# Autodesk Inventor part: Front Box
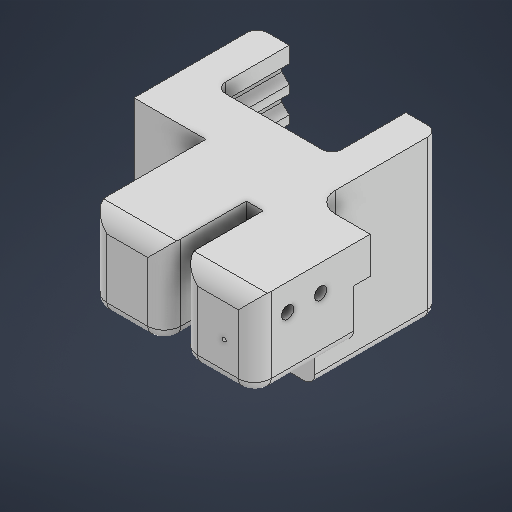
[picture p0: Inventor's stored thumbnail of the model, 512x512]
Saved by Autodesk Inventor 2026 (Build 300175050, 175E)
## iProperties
Created: 2023-12
Part Number: Front Box
Material: Generic
Document SubType Name: Modeling
Designer: Andrew
Density: 1 g/cm^3
Appearance: Default
Author: Andrew
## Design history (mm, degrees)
sketch "Sketch1"
  geometry: L1 (76.2, -76.2)-(-76.2, -76.2); L2 (-76.2, -76.2)-(-76.2, 76.2); L3 (-76.2, 76.2)-(76.2, 76.2); L4 (76.2, 76.2)-(76.2, -76.2); 1 further point
  constraints: 8 end point, 2 parallel, 1 horizontal, 1 perpendicular
  dimensions: "d0" = 152.4 distance between parallel lines of L3 L1 (derived); "d1" = 152.4 distance between parallel lines of L4 L2; "d2" = 76.2 distance from line of point (0, 0) L1 (= 0.5 x d0); "d3" = 76.2 distance from line of L2 point (0, 0) (= 0.5 x d1)
extrude "Extrusion1" new body sketch "Sketch1" distance "d4" = 5.08; taper "d5" = 0 deg
sketch "Sketch2"
  geometry: L1 (-76.2, -76.2)-(76.2, -76.2) reference; L2 (76.2, -76.2)-(76.2, 76.2) reference; L3 (76.2, 76.2)-(-76.2, 76.2) reference; L4 (-76.2, 76.2)-(-76.2, -76.2) reference; L5 (-71.12, 71.12)-(71.12, 71.12); L6 (71.12, 71.12)-(71.12, -71.12); L7 (71.12, -71.12)-(-71.12, -71.12); L8 (-71.12, -71.12)-(-71.12, 71.12); L9 (-71.12, 2.54)-(71.12, 2.54); L10 (71.12, 2.54)-(71.12, -2.54); L11 (71.12, -2.54)-(-71.12, -2.54); L12 (-71.12, -2.54)-(-71.12, 2.54); L13 (-2.54, 71.12)-(2.54, 71.12); L14 (2.54, 71.12)-(2.54, -71.12); L15 (2.54, -71.12)-(-2.54, -71.12); L16 (-2.54, -71.12)-(-2.54, 71.12); 11 further points
  constraints: 24 end point, 6 parallel, 4 point on line, 3 horizontal, 3 perpendicular, 2 midpoint
  dimensions: "d6" = 5.08 distance between parallel lines of L5 L3; "d7" = 5.08 distance between parallel lines of L4 L8; "d8" = 5.08 distance between parallel lines of L2 L6; "d9" = 5.08 distance between parallel lines of L1 L7; "d10" = 5.08 distance between parallel lines of L11 L9; "d11" = 5.08 distance between parallel lines of L16 L14; "d207" = 152.4 distance between parallel lines of L1 L3 (derived); "d208" = 76.2 distance from line of L1 point (-71.12, 0) (derived); "d209" = 76.2 distance from line of point (0, -71.12) L4 (derived)
extrude "Extrusion2" join sketch "Sketch2" distance "d14" = 25.4; taper "d15" = 0 deg
sketch "Sketch3"
  geometry: L1 (0, 30.48)-(152.4, 30.48) reference; L2 (104.14, 30.48)-(93.98, 30.48); L3 (93.98, 30.48)-(93.98, -19.05); L4 (93.98, -19.05)-(104.14, -19.05); L5 (104.14, -19.05)-(104.14, 30.48); L6 (58.42, 30.48)-(48.26, 30.48); L7 (48.26, 30.48)-(48.26, -19.05); L8 (48.26, -19.05)-(58.42, -19.05); L9 (58.42, -19.05)-(58.42, 30.48); L10 (152.4, 0)-(152.4, 30.48) reference; L11 (0, 0)-(152.4, 0) reference; 7 further points
  constraints: 16 end point, 5 midpoint, 4 parallel, 3 point on line, 2 horizontal, 2 perpendicular
  dimensions: "d18" = 10.16 distance from line of L3 point (104.14, 5.715); "d19" = 10.16 distance from line of L7 point (58.42, 5.715); "d20" = 35.56 distance between parallel lines of L9 L3; "d173" = 19.05 distance between parallel lines of L11 L4; "d198" = 17.78 distance from line of point (76.2, 30.48) L3 (derived)
extrude "Extrusion3" join sketch "Sketch3" distance "d23" = 38.1; taper "d24" = 0 deg
sketch "Sketch4"
  geometry: L1 (93.98, 30.48)-(93.98, -19.05) reference; L2 (93.98, 25.4)-(58.42, 25.4); L3 (58.42, 25.4)-(58.42, 30.48); L4 (58.42, 30.48)-(93.98, 30.48); L5 (93.98, 30.48)-(93.98, 25.4); L6 (58.42, -19.05)-(58.42, 30.48) reference; L7 (58.42, 30.48)-(93.98, 30.48) reference; 2 further points
  constraints: 8 end point, 2 parallel, 1 horizontal, 1 perpendicular, 1 point on line
  dimensions: "d25" = 0 distance between parallel lines of L6 L3; "d26" = 0 distance between parallel lines of L7 L4; "d27" = 5.08 distance between parallel lines of L4 L2
extrude "Extrusion4" join sketch "Sketch4" stored distance "d28" = 25.4; taper "d29" = 0 deg
sketch "Sketch5"
  geometry: L1 (7.62, -33.02)-(48.26, -33.02); L2 (48.26, -33.02)-(48.26, 0); L3 (48.26, 0)-(7.62, 0); L4 (7.62, 0)-(7.62, -33.02); L5 (104.14, 0)-(-48.26, 0) reference; L6 (10.16, -38.1)-(0, -38.1) reference; L7 (45.72, -38.1)-(10.16, -38.1) reference; 6 further points; 2 other entities
  constraints: 8 end point, 2 parallel, 1 horizontal, 1 midpoint, 1 perpendicular, 2 other
  dimensions: "d32" = 33.02 distance between parallel lines of L1 L3; "d174" = 2.54 dimension on L4; "d175" = 2.54 dimension on L2; "d177" = 38.1 distance between parallel lines of L6 L3
extrude "Extrusion5" cut sketch "Sketch5" distance "d34" = 2.54; taper "d35" = 0 deg
sketch "Sketch8"
  geometry: L1 (55.88, 25.4)-(96.52, 25.4); L2 (96.52, 25.4)-(96.52, 19.812); L3 (96.52, 19.812)-(55.88, 19.812); L4 (55.88, 19.812)-(55.88, 25.4); L5 (58.42, -19.05)-(58.42, 25.4) reference; L6 (93.98, 25.4)-(93.98, -19.05) reference; L7 (96.52, 11.684)-(55.88, 11.684); L8 (55.88, 11.684)-(55.88, 17.272); L9 (55.88, 17.272)-(96.52, 17.272); L10 (96.52, 17.272)-(96.52, 11.684); L11 (96.52, 3.556)-(55.88, 3.556); L12 (55.88, 3.556)-(55.88, 9.144); L13 (55.88, 9.144)-(96.52, 9.144); L14 (96.52, 9.144)-(96.52, 3.556); L15 (96.52, -4.572)-(55.88, -4.572); L16 (55.88, -4.572)-(55.88, 1.016); L17 (55.88, 1.016)-(96.52, 1.016); L18 (96.52, 1.016)-(96.52, -4.572); L19 (96.52, -12.7)-(55.88, -12.7); L20 (55.88, -12.7)-(55.88, -7.112); L21 (55.88, -7.112)-(96.52, -7.112); L22 (96.52, -7.112)-(96.52, -12.7); L23 (96.52, -15.24)-(55.88, -15.24); L24 (55.88, -15.24)-(55.88, -20.828); L25 (55.88, -20.828)-(96.52, -20.828); L26 (96.52, -20.828)-(96.52, -15.24); L27 (96.52, -28.956)-(55.88, -28.956); L28 (55.88, -28.956)-(55.88, -23.368); L29 (55.88, -23.368)-(96.52, -23.368); L30 (96.52, -23.368)-(96.52, -28.956); L31 (96.52, -37.084)-(55.88, -37.084); L32 (55.88, -37.084)-(55.88, -31.496); L33 (55.88, -31.496)-(96.52, -31.496); L34 (96.52, -31.496)-(96.52, -37.084); 15 further points
  constraints: 64 end point, 16 parallel, 13 collinear, 8 horizontal, 8 perpendicular, 2 midpoint, 2 other
  dimensions: "d39" = 5.588 dimension on L3; "d40" = 2.54 distance between parallel lines of L5 L4; "d41" = 2.54 distance between parallel lines of L6 L2; "d117" = 5.588 distance between parallel lines of L9 L7 (= d39); "d119" = 2.54 distance between parallel lines of L3 L9; "d120" = 2.54 distance between parallel lines of L7 L13 (= d119); "d121" = 5.588 distance between parallel lines of L13 L11 (= d117); "d122" = 5.588 distance between parallel lines of L17 L15 (= d121); "d123" = 2.54 distance between parallel lines of L11 L17 (= d120); "d178" = 5.588 distance between parallel lines of L21 L19 (derived); "d179" = 2.54 distance between parallel lines of L15 L21 (derived); "d180" = 5.588 distance from line of point (76.2, -15.24) L25 (derived); "d181" = 2.54 distance between parallel lines of L19 L23 (derived); "d199" = 2.54 distance from line of point (55.88, -18.034) L5 (derived); "d200" = 5.588 distance between parallel lines of L29 L27 (derived); "d201" = 5.588 distance between parallel lines of L33 L31 (derived); "d202" = 2.54 distance between parallel lines of L25 L29 (derived); "d203" = 2.54 distance between parallel lines of L27 L33 (derived)
extrude "Extrusion7" cut sketch "Sketch8" stored distance "d42" = 31.75; taper "d43" = 0 deg
fillet "Fillet1" dims "d49" = 3.175
sketch "Sketch10"
  geometry: L1 (2.54, -2.54)-(71.12, -2.54) reference; L2 (71.12, -2.54)-(71.12, -71.12) reference; L3 (71.12, -71.12)-(2.54, -71.12) reference; L4 (2.54, -71.12)-(2.54, -2.54) reference; L5 (71.12, 71.12)-(2.54, 71.12) reference; L6 (2.54, 2.54)-(2.54, 71.12) reference; L7 (2.54, 71.12)-(71.12, 71.12) reference; L8 (71.12, 71.12)-(71.12, 2.54) reference; L9 (71.12, 2.54)-(2.54, 2.54) reference; L10 (-2.54, 2.54)-(-71.12, 2.54) reference; L11 (-71.12, 2.54)-(-71.12, 71.12) reference; L12 (-71.12, 71.12)-(-2.54, 71.12) reference; L13 (-2.54, 71.12)-(-2.54, 2.54) reference; L14 (-2.54, -2.54)-(-2.54, -71.12) reference; L15 (-2.54, -71.12)-(-71.12, -71.12) reference; L16 (-71.12, -71.12)-(-71.12, -2.54) reference; L17 (-71.12, -2.54)-(-2.54, -2.54) reference; 3 further points
extrude "Extrusion9" cut sketch "Sketch10" distance "d54" = 25.4; taper "d55" = 0 deg
sketch "Sketch12"
  geometry: L1 (2.54, 71.12)-(71.12, 71.12) reference; L2 (71.12, 71.12)-(55.88, 71.12); L3 (55.88, 71.12)-(55.88, 55.88); L4 (55.88, 55.88)-(71.12, 55.88); L5 (71.12, 55.88)-(71.12, 71.12); L6 (71.12, -71.12)-(2.54, -71.12) reference; L7 (71.12, -71.12)-(55.88, -71.12); L8 (55.88, -71.12)-(55.88, -55.88); L9 (55.88, -55.88)-(71.12, -55.88); L10 (71.12, -55.88)-(71.12, -71.12); L11 (-71.12, 71.12)-(-55.88, 71.12); L12 (-55.88, 71.12)-(-55.88, 55.88); L13 (-55.88, 55.88)-(-71.12, 55.88); L14 (-71.12, 55.88)-(-71.12, 71.12); L15 (-71.12, -71.12)-(-71.12, -2.54) reference; L16 (-71.12, -71.12)-(-55.88, -71.12); L17 (-55.88, -71.12)-(-55.88, -55.88); L18 (-55.88, -55.88)-(-71.12, -55.88); L19 (-71.12, -55.88)-(-71.12, -71.12); L20 (71.12, -2.54)-(71.12, -71.12) reference; L21 (-71.12, 2.54)-(-71.12, 71.12) reference; L22 (71.12, 71.12)-(71.12, 2.54) reference; L23 (76.2, 73.025)-(76.2, -73.025) reference; L24 (-76.2, -73.025)-(-76.2, 73.025) reference; L25 (-73.025, 76.2)-(73.025, 76.2) reference; C1 r 1.905 at (60.96, 60.96); C2 r 1.905 at (60.96, -60.96); C3 r 1.905 at (-60.96, 60.96); C4 r 1.905 at (-60.96, -60.96); 17 further points; 2 other entities
  constraints: 32 end point, 8 parallel, 6 midpoint, 4 centre point, 4 horizontal, 4 perpendicular, 2 other
  dimensions: "d56" = 15.24 distance between parallel lines of L6 L9 (= d82); "d57" = 15.24 distance between parallel lines of L20 L8 (= d58); "d58" = 15.24 distance from line of L15 point (-55.88, -63.5); "d59" = 15.24 distance from line of L16 point (-63.5, -55.88); "d64" = 3.81 diameter of C3; "d65" = 3.81 diameter of C4 (= d64); "d66" = 3.81 diameter of C2 (= d64); "d67" = 3.81 diameter of C1 (= d64); "d78" = 15.24 dimension on C2.centre; "d79" = 15.24 distance from line of L23 C2.centre; "d85" = 15.24 distance from line of point (63.5, 71.12) L4 (= d78); "d86" = 15.24 distance between parallel lines of L5 L3 (= d57); "d87" = 15.24 distance between parallel lines of L14 L12 (= d82); "d88" = 15.24 distance between parallel lines of L13 L11 (= d58); "d89" = 15.24 distance from line of C3.centre L25 (= d82); "d90" = 15.24 dimension on C4.centre (= d78); "d91" = 15.24 distance from line of L24 C4.centre (= d79); "d92" = 15.24 distance from line of L24 C3.centre (= d58); "d93" = 15.24 distance from line of L23 C1.centre (= d57); "d94" = 15.24 distance from line of L25 C1.centre (= d78)
extrude "Extrusion10" join sketch "Sketch12" stored distance "d76" = 25.4; taper "d77" = 0 deg
fillet "Fillet2" dims "d95" = 3.175
sketch "Sketch13"
  geometry: L1 (-62.573, -58.166)-(-59.347, -58.166); L2 (-59.347, -58.166)-(-57.734, -60.96); L3 (-57.734, -60.96)-(-59.347, -63.754); L4 (-59.347, -63.754)-(-62.573, -63.754); L5 (-62.573, -63.754)-(-64.186, -60.96); L6 (-64.186, -60.96)-(-62.573, -58.166); L7 (-59.347, 63.754)-(-57.734, 60.96); L8 (-57.734, 60.96)-(-59.347, 58.166); L9 (-59.347, 58.166)-(-62.573, 58.166); L10 (-62.573, 58.166)-(-64.186, 60.96); L11 (-64.186, 60.96)-(-62.573, 63.754); L12 (-62.573, 63.754)-(-59.347, 63.754); L13 (59.347, 63.754)-(62.573, 63.754); L14 (62.573, 63.754)-(64.186, 60.96); L15 (64.186, 60.96)-(62.573, 58.166); L16 (62.573, 58.166)-(59.347, 58.166); L17 (59.347, 58.166)-(57.734, 60.96); L18 (57.734, 60.96)-(59.347, 63.754); L19 (59.347, -58.166)-(62.573, -58.166); L20 (62.573, -58.166)-(64.186, -60.96); L21 (64.186, -60.96)-(62.573, -63.754); L22 (62.573, -63.754)-(59.347, -63.754); L23 (59.347, -63.754)-(57.734, -60.96); L24 (57.734, -60.96)-(59.347, -58.166); C1 r 1.905 at (-60.96, -60.96) reference; C2 r 1.905 at (-60.96, 60.96) reference; C3 r 1.905 at (60.96, 60.96) reference; C4 r 1.905 at (60.96, -60.96) reference; 6 further points
  constraints: 48 end point, 4 coincident, 4 horizontal, 1 midpoint, 52 other
  dimensions: "d96" = 5.588 distance between parallel lines of L21 L24; "d97" = 5.588 distance between parallel lines of L15 L18 (= d96); "d98" = 5.588 distance from line of point (-58.54, 59.563) L11 (= d96); "d99" = 5.588 distance between parallel lines of L3 L6 (= d96)
extrude "Extrusion11" cut sketch "Sketch13" distance "d100" = 25.4; taper "d101" = 0 deg
sketch "Sketch22"
  geometry: L1 (52.705, 0)-(-3.175, 0) reference; L2 (49.53, 0)-(49.53, -34.925) reference; L3 (0, 0)-(49.53, 0); L4 (49.53, 0)-(49.53, -5.08); L5 (49.53, -5.08)-(0, -5.08); L6 (0, -5.08)-(0, 0); L7 (0, -34.925)-(0, 0) reference; 4 further points
  constraints: 8 end point, 2 parallel, 2 point on line, 1 horizontal, 1 perpendicular
  dimensions: "d182" = 0 distance between parallel lines of L7 L6; "d183" = 5.08 distance between parallel lines of L3 L5
extrude "Extrusion19" join sketch "Sketch22" stored distance "d184" = 25.4; taper "d185" = 0 deg
chamfer "Chamfer2" distance "d124" = 2.286; stored, may be unused: second distance "d125" = 3.175, angle "d126" = 45 deg
sketch "Sketch17"
  geometry: L1 (-12.7, 114.3)-(12.7, 114.3); L2 (12.7, 114.3)-(12.7, 91.44); L3 (12.7, 91.44)-(-12.7, 91.44); L4 (-12.7, 91.44)-(-12.7, 114.3); L5 (27.94, 79.375)-(27.94, 111.125) reference; L6 (-27.94, 79.375)-(-27.94, 111.125) reference; L7 (-24.765, 114.3)-(24.765, 114.3) reference; 2 further points
  constraints: 8 end point, 2 parallel, 1 horizontal, 1 midpoint, 1 perpendicular
  dimensions: "d141" = 25.4 distance between parallel lines of L2 L4; "d142" = 55.88 distance between parallel lines of L5 L6 (derived); "d143" = 27.94 distance from line of L5 point (0, 114.3) (derived); "d144" = 0 distance between parallel lines of L7 L1; "d145" = 22.86 distance between parallel lines of L3 L1
extrude "Extrusion15" cut sketch "Sketch17" extent not by distance; stored distance "d146" = 0; taper "d147" = 0 deg
fillet "Fillet5" dims "d148" = 3.175
sketch "Sketch19"
  geometry: L1 (93.345, 1.016)-(93.345, -4.572) reference; L2 (45.085, 0)-(45.085, 30.48) reference; L3 (0, 30.48)-(41.91, 30.48) reference; L4 (0, 0)-(41.91, 0) reference; L5 (104.14, 0)-(146.05, 0) reference; C1 r 0.635 at (108.585, 15.24); C2 r 0.635 at (37.465, 15.24); 10 further points; 1 other entity
  constraints: 2 centre point, 1 midpoint, 2 other
  dimensions: "d156" = 1.27 diameter of C1; "d157" = 1.27 diameter of C2; "d187" = 71.12 distance of C1.centre C2.centre; "d190" = 7.62 distance from line of L2 C2.centre; "d204" = 30.48 distance between parallel lines of L3 L4 (derived); "d205" = 15.24 distance from line of L4 C2.centre (derived); "d206" = 15.24 distance from line of C1.centre L5 (derived)
extrude "Extrusion17" cut sketch "Sketch19" distance "d163" = 12.7; taper "d164" = 0 deg
sketch "Sketch20"
  geometry: C1 r 0.635 at (29.845, 15.24) reference; C2 r 0.635 at (-41.275, 15.24) reference; C3 r 1.905 at (-41.275, 15.24); C4 r 1.905 at (29.845, 15.24); 1 further point
  constraints: 2 centre point, 2 coincident
  dimensions: "d165" = 3.81 diameter of C4; "d166" = 3.81 diameter of C3
extrude "Extrusion18" join sketch "Sketch20" distance "d167" = 6.35; taper "d168" = 0 deg
chamfer "Chamfer3" distance "d169" = 6.35; stored, may be unused: second distance "d170" = 3.175, angle "d171" = 45 deg
sketch "Sketch23"
  geometry: L1 (46.173, 31.431)-(71.12, 31.431); L2 (71.12, 31.431)-(71.12, 71.12); L3 (71.12, 71.12)-(46.173, 71.12); L4 (46.173, 71.12)-(46.173, 31.431); L5 (46.173, -43.871)-(71.12, -43.871); L6 (71.12, -43.871)-(71.12, -71.12); L7 (71.12, -71.12)-(46.173, -71.12); L8 (46.173, -71.12)-(46.173, -43.871); L9 (-32.457, -43.871)-(-71.12, -43.871); L10 (-71.12, -43.871)-(-71.12, -71.12); L11 (-71.12, -71.12)-(-32.457, -71.12); L12 (-32.457, -71.12)-(-32.457, -43.871); L13 (-46.383, 37.781)-(-71.12, 37.781); L14 (-71.12, 37.781)-(-71.12, 71.12); L15 (-71.12, 71.12)-(-46.383, 71.12); L16 (-46.383, 71.12)-(-46.383, 37.781); L17 (5.715, 71.12)-(52.705, 71.12) reference; L18 (71.12, 52.705)-(71.12, 5.715) reference; L19 (52.705, -71.12)-(5.715, -71.12) reference; L20 (-71.12, -52.705)-(-71.12, -5.715) reference; L21 (-71.12, 5.715)-(-71.12, 52.705) reference; L22 (-52.705, 71.12)-(-5.715, 71.12) reference; 1 further point
  constraints: 32 end point, 8 parallel, 6 collinear, 4 horizontal, 4 perpendicular, 4 point on line
extrude "Extrusion20" cut sketch "Sketch23" distance "d191" = 20.32; taper "d192" = 0 deg
chamfer "Chamfer4" distance "d193" = 6.35; stored, may be unused: second distance "d194" = 3.175, angle "d195" = 45 deg
fillet "Fillet6" dims "d196" = 3.175
sketch "Sketch24"
  geometry: L1 (122.676, 162.487)-(-169.507, 162.487); L2 (-169.507, 162.487)-(-169.507, -76.2); L3 (-169.507, -76.2)-(122.676, -76.2); L4 (122.676, -76.2)-(122.676, 162.487); L5 (24.765, -76.2)-(-24.765, -76.2) reference; 1 further point
  constraints: 8 end point, 2 parallel, 1 horizontal, 1 perpendicular
  dimensions: "d210" = 0 distance between parallel lines of L5 L3
extrude "Extrusion21" cut sketch "Sketch24" extent not by distance; stored distance "d211" = 0; taper "d212" = 0 deg
workplane "Work Plane1"
sketch "Sketch26"
  geometry: L1 (19.05, -76.2)-(30.48, -76.2); L2 (30.48, -76.2)-(30.48, -70.993); L3 (30.48, -70.993)-(19.05, -70.993); L4 (19.05, -70.993)-(19.05, -76.2); L5 (30.48, -70.993)-(12.7, -70.993); L6 (12.7, -70.993)-(12.7, -65.913); L7 (12.7, -65.913)-(30.48, -65.913); L8 (30.48, -65.913)-(30.48, -70.993); L9 (30.48, -79.375)-(30.48, -111.125) reference; L10 (30.48, -76.2)-(0, -76.2) reference; 6 further points
  constraints: 16 end point, 4 midpoint, 4 parallel, 2 horizontal, 2 perpendicular
  dimensions: "d222" = 11.43 distance between parallel lines of L2 L4; "d223" = 5.08 distance from line of L7 point (24.765, -70.993); "d224" = 0 distance between parallel lines of L9 L2; "d225" = 0 distance from line of L10 point (24.765, -76.2); "d227" = 5.207 distance between parallel lines of L5 L10; "d228" = 17.78 distance of point (30.48, -68.453) point (12.7, -68.453)
extrude "Extrusion23" join sketch "Sketch26" stored distance "d229" = 50.8; taper "d230" = 0 deg
fillet "Fillet8" dims "d231" = 1.27
sketch "Sketch27"
  geometry: L1 (30.48, 0)-(33.655, 0) reference; L2 (50.8, 0)-(28.003, 0); L3 (28.003, 0)-(28.003, -16.51); L4 (28.003, -16.51)-(50.8, -16.51); L5 (50.8, -16.51)-(50.8, 0); L6 (0, 0)-(22.796, 0); L7 (22.796, 0)-(22.797, -16.51); L8 (22.797, -16.51)-(0, -16.51); L9 (0, -16.51)-(0, 0); L10 (50.8, 0)-(50.8, -16.51) reference; L11 (0, -16.51)-(0, 0) reference; L12 (50.8, -16.51)-(0, -16.51) reference; 6 further points
  constraints: 16 end point, 4 parallel, 3 collinear, 2 horizontal, 2 midpoint, 2 perpendicular, 2 point on line
  dimensions: "d232" = 5.207 distance between parallel lines of L3 L7; "d233" = 0 distance from line of L10 point (50.8, -8.255); "d234" = 22.7965 distance from line of L10 point (28.003, -8.255) (derived); "d235" = 50.8 distance between parallel lines of L11 L10 (derived)
extrude "Extrusion24" join sketch "Sketch27" distance "d238" = 25.4; taper "d239" = 0 deg
fillet "Fillet10" dims "d241" = 5.08
sketch "Sketch28"
  geometry: L1 (76.2, 30.48)-(45.593, 30.48) reference; L2 (65.913, 13.97)-(45.593, 13.97) reference; L3 (76.2, 19.05)-(76.2, 0) reference; L4 (45.593, 13.97)-(45.593, 30.48) reference; C1 r 1.905 at (50.673, 22.225); C2 r 1.905 at (60.833, 22.225); 4 further points
  constraints: 3 midpoint, 2 centre point
  dimensions: "d242" = 3.81 diameter of C1; "d243" = 16.51 distance between parallel lines of L1 L2 (derived); "d245" = 0 vertical distance of point (45.593, 22.225) C1.centre; "d246" = 20.32 distance of L2.end L2.start (derived); "d247" = 5.08 distance from line of L4 C1.centre (derived); "d254" = 3.81 diameter of C2 (derived); "d255" = 15.24 distance from line of L4 C2.centre (derived); "d256" = 0 vertical distance of point (45.593, 22.225) C2.centre
extrude "Extrusion25" cut sketch "Sketch28" extent not by distance; stored distance "d248" = 0; taper "d249" = 0 deg
sketch "Sketch29"
  geometry: L1 (-52.257, 19.482)-(-53.841, 22.225); L2 (-53.841, 22.225)-(-52.257, 24.968); L3 (-52.257, 24.968)-(-49.089, 24.968); L4 (-49.089, 24.968)-(-47.505, 22.225); L5 (-47.505, 22.225)-(-49.089, 19.482); L6 (-49.089, 19.482)-(-52.257, 19.482); L7 (-62.417, 19.482)-(-64.001, 22.225); L8 (-64.001, 22.225)-(-62.417, 24.968); L9 (-62.417, 24.968)-(-59.249, 24.968); L10 (-59.249, 24.968)-(-57.665, 22.225); L11 (-57.665, 22.225)-(-59.249, 19.482); L12 (-59.249, 19.482)-(-62.417, 19.482); C1 r 1.905 at (-50.673, 22.225) reference; C2 r 1.905 at (-60.833, 22.225) reference; 5 further points
  constraints: 24 end point, 2 coincident, 2 horizontal, 2 midpoint, 26 other
  dimensions: "d251" = 5.4864 distance between parallel lines of L3 L6; "d257" = 5.4864 distance between parallel lines of L9 L12
extrude "Extrusion26" cut sketch "Sketch29" distance "d252" = 5.08; taper "d253" = 0 deg
sketch "Sketch30"
  geometry: L1 (-56.644, 76.2)-(-27.94, 76.2); L2 (-27.94, 76.2)-(-27.94, 124.943); L3 (-27.94, 124.943)-(-56.644, 124.943); L4 (-56.644, 124.943)-(-56.644, 76.2); L5 (58.015, 76.2)-(27.94, 76.2); L6 (27.94, 76.2)-(27.94, 128.542); L7 (27.94, 128.542)-(58.015, 128.542); L8 (58.015, 128.542)-(58.015, 76.2); L9 (-27.94, 79.375)-(-27.94, 111.125) reference; L10 (27.94, 79.375)-(27.94, 111.125) reference; L11 (31.115, 76.2)-(27.94, 76.2) reference; L12 (24.765, 76.2)-(-24.765, 76.2) reference; 2 further points
  constraints: 16 end point, 4 parallel, 2 horizontal, 2 perpendicular, 1 midpoint
  dimensions: "d258" = 0 distance between parallel lines of L9 L2; "d259" = 0 distance between parallel lines of L6 L10; "d282" = 0 distance from line of L11 point (42.978, 76.2); "d283" = 0 distance between parallel lines of L12 L1
extrude "Extrusion27" cut sketch "Sketch30" extent not by distance; stored distance "d260" = 0; taper "d261" = 0 deg
sketch "Sketch31"
  geometry: L1 (-18.034, 122.551)-(18.034, 122.551); L2 (18.034, 122.551)-(18.034, 94.615); L3 (14.859, 91.44)-(-14.859, 91.44); L4 (-18.034, 94.615)-(-18.034, 122.551); L5 (9.525, 91.44)-(-9.525, 91.44) reference; L6 (-18.034, 114.3)-(-18.034, 81.28) reference; L7 (18.034, 81.28)-(18.034, 114.3) reference; A1 r 3.175 centre (-14.859, 94.615) between (-18.034, 94.615) and (-14.859, 91.44); A2 r 3.175 centre (14.859, 94.615) between (14.859, 91.44) and (18.034, 94.615); 1 further point
  constraints: 8 end point, 4 point on circle, 4 tangent, 2 centre point, 2 parallel, 1 equal radius, 1 horizontal, 1 perpendicular
  dimensions: "d262" = 0 distance between parallel lines of L5 L3; "d263" = 0 distance between parallel lines of L6 L4; "d264" = 0 distance between parallel lines of L7 L2; "d265" = 3.175 radius of A1 (derived)
extrude "Extrusion28" cut sketch "Sketch31" distance "d266" = 5.08; taper "d267" = 0 deg
sketch "Sketch32"
  geometry: L1 (58.166, -33.929)-(94.234, -33.929); L2 (94.234, -33.929)-(94.234, 25.4); L3 (94.234, 25.4)-(58.166, 25.4); L4 (58.166, 25.4)-(58.166, -33.929); L5 (91.059, 25.4)-(61.341, 25.4) reference; 3 further points
  constraints: 8 end point, 2 parallel, 1 horizontal, 1 perpendicular
  dimensions: "d268" = 0 distance from line of point (94.234, 1.016) L2; "d269" = 0 distance from line of point (58.166, 1.016) L4; "d270" = 0 distance between parallel lines of L5 L3
extrude "Extrusion29" cut sketch "Sketch32" stored distance "d271" = 25.4; taper "d272" = 0 deg
sketch "Sketch33"
  geometry: L1 (38.354, 2.54)-(40.64, 2.54) reference; L2 (0, 8.636)-(2.286, 6.35) reference; L3 (38.354, 2.54)-(2.286, 2.54); L4 (2.286, 2.54)-(2.286, 6.35); L5 (2.286, 6.35)-(38.354, 6.35); L6 (38.354, 6.35)-(38.354, 2.54); 1 further point
  constraints: 8 end point, 2 parallel, 1 horizontal, 1 perpendicular
extrude "Extrusion30" join sketch "Sketch33" distance "d273" = 2.286; taper "d274" = 0 deg
chamfer "Chamfer5" distance "d279" = 2.286; stored, may be unused: second distance "d280" = 3.175, angle "d281" = 45 deg
sketch "Sketch35"
  geometry: L1 (0, 0)-(0, 20.32) reference; L2 (22.796, 0)-(0, 0) reference; L3 (22.796, 0)-(22.796, 20.32) reference; L4 (-28.003, 0)-(-28.003, 20.32) reference; L5 (-5.207, 0)-(-28.003, 0) reference; L6 (-5.207, 0)-(-5.207, 20.32) reference; L7 (-22.923, 25.4)-(-10.287, 25.4) reference; L8 (5.08, 25.4)-(17.716, 25.4) reference; L9 (22.796, -5.08)-(0, -5.08); L10 (0, -5.08)-(0, 20.32); L11 (0, 20.32)-(22.796, 20.32); L12 (22.796, 20.32)-(22.796, -5.08); L13 (-28.003, -5.08)-(22.796, -5.08) reference; L14 (-28.003, 20.32)-(-5.207, 20.32); L15 (-5.207, 20.32)-(-5.207, -5.08); L16 (-5.207, -5.08)-(-28.003, -5.08); L17 (-28.003, -5.08)-(-28.003, 20.32); A1 r 5.08 centre (-10.287, 20.32) between (-5.207, 20.32) and (-10.287, 25.4) reference; A2 r 5.08 centre (-22.923, 20.32) between (-22.923, 25.4) and (-28.003, 20.32) reference; A3 r 5.08 centre (5.08, 20.32) between (5.08, 25.4) and (0, 20.32) reference; A4 r 5.08 centre (17.716, 20.32) between (22.796, 20.32) and (17.716, 25.4) reference; 6 further points
  constraints: 16 end point, 4 parallel, 2 horizontal, 2 perpendicular, 1 point on line
  dimensions: "d285" = 0 distance between parallel lines of L3 L12; "d286" = 0 distance between parallel lines of L13 L9; "d287" = 0 distance between parallel lines of L6 L15
extrude "Extrusion31" join sketch "Sketch35" distance "d288" = 10.16; taper "d289" = 0 deg
fillet "Fillet11" dims "d290" = 3.175
sketch "Sketch36"
  geometry: L1 (-104.14, 30.48)-(-81.915, 30.48) reference; L2 (-104.14, -15.875)-(-104.14, 30.48) reference; L3 (-31.115, 6.985)-(-31.115, 30.48) reference; C1 r 0.635 at (-40.576, 15.24); 1 further point
  constraints: 1 centre point
  dimensions: "d291" = 15.24 distance from line of L1 C1.centre; "d292" = 1.27 diameter of C1; "d294" = 9.4615 distance from line of C1.centre L3
extrude "Extrusion32" cut sketch "Sketch36" extent not by distance; stored distance "d295" = 0; taper "d296" = 0 deg
fillet "Fillet12" dims "d297" = 6.35
sketch "Sketch37"
  geometry: L1 (50.705, 123.356)-(-45.125, 123.356); L2 (-45.125, 123.356)-(-45.125, 19.263); L3 (-45.125, 19.263)-(50.705, 19.263); L4 (50.705, 19.263)-(50.705, 123.356); 1 further point
  constraints: 8 end point, 2 parallel, 1 horizontal, 1 perpendicular
extrude "Extrusion33" cut sketch "Sketch37" distance "d298" = 0.127; taper "d299" = 0 deg
body "Solid1"
node "Projected Loop1"
node "Projected Loop2"
node "Projected Loop3"
node "Projected Loop4"
node "Projected Loop5"
node "Projected Loop7"
node "Projected Loop8"
other parameters: "d82" = 15.24 (= d78), "d284" = 19.685
